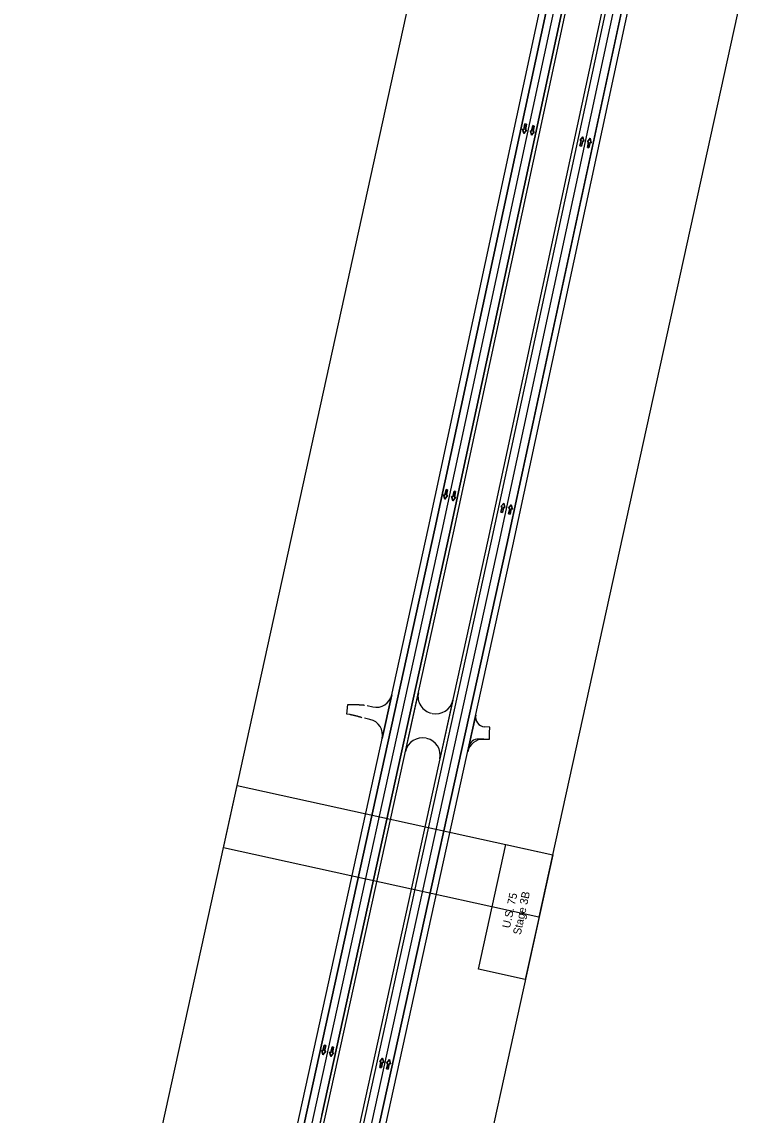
# Model space of a CAD drawing. Extents: x 14104283 to 14120882, y 8635219 to 8671666.
# Drawn here: x 14107966 to 14109111, y 8642294 to 8644002 of the extents above; entities that cross this region are included whole.
import ezdxf

# ---------------------------------------------------------------- set-up
doc = ezdxf.new("R2010")
doc.units = 0
for name, color, linetype in [('Cell', 7, 'Continuous'), ('dsnNonPlotable', 7, 'Continuous'), ('dsnPaintExistingBrokenLaneLineWhite', 7, 'Continuous'), ('dsnPaintExistingEdgeLineLeftYellow', 7, 'Continuous'), ('dsnPaintExistingEdgeLineRightWhite', 7, 'Continuous'), ('dsnShadingPaved', 7, 'Continuous'), ('dsnStgShadingPrevPav', 7, 'Continuous'), ('dsnTextOverlapEven', 7, 'Continuous')]:
    doc.layers.add(name, color=color, linetype=linetype)

msp = doc.modelspace()

# ---------------------------------------------------------------- linework, layer by layer
at = {"layer": 'Cell'}
for points in [[(14108752.6, 8643842.5), (14108755.1, 8643842), (14108753.2, 8643833.5), (14108755.1, 8643833.1), (14108750.7, 8643827.6), (14108748.9, 8643834.4), (14108750.8, 8643834)], [(14108764.7, 8643839.9), (14108767.2, 8643839.3), (14108765.3, 8643830.8), (14108767.1, 8643830.4), (14108762.7, 8643825), (14108761, 8643831.7), (14108762.8, 8643831.3)], [(14108841.1, 8643807.7), (14108838.6, 8643808.2), (14108840.5, 8643816.8), (14108838.7, 8643817.2), (14108843, 8643822.6), (14108844.8, 8643815.8), (14108842.9, 8643816.2)], [(14108852.6, 8643805.1), (14108850.2, 8643805.7), (14108852, 8643814.2), (14108850.2, 8643814.6), (14108854.6, 8643820.1), (14108856.3, 8643813.3), (14108854.5, 8643813.7)], [(14108629.2, 8643271.5), (14108631.6, 8643270.9), (14108629.8, 8643262.4), (14108631.6, 8643262), (14108627.2, 8643256.5), (14108625.5, 8643263.3), (14108627.3, 8643262.9)], [(14108641.7, 8643268.7), (14108644.1, 8643268.2), (14108642.3, 8643259.6), (14108644.1, 8643259.2), (14108639.7, 8643253.8), (14108638, 8643260.6), (14108639.8, 8643260.2)], [(14108717.5, 8643235.4), (14108715.1, 8643235.9), (14108716.9, 8643244.5), (14108715.1, 8643244.9), (14108719.5, 8643250.3), (14108721.2, 8643243.5), (14108719.4, 8643243.9)], [(14108729.3, 8643232.8), (14108726.8, 8643233.3), (14108728.7, 8643241.9), (14108726.9, 8643242.3), (14108731.2, 8643247.7), (14108733, 8643240.9), (14108731.1, 8643241.3)], [(14108438.8, 8642403.3), (14108441.2, 8642402.8), (14108439.4, 8642394.2), (14108441.2, 8642393.8), (14108436.8, 8642388.4), (14108435.1, 8642395.2), (14108436.9, 8642394.8)], [(14108451, 8642400.7), (14108453.4, 8642400.1), (14108451.6, 8642391.6), (14108453.4, 8642391.2), (14108449, 8642385.7), (14108447.3, 8642392.5), (14108449.1, 8642392.1)], [(14108528.1, 8642368.3), (14108525.7, 8642368.8), (14108527.5, 8642377.4), (14108525.7, 8642377.8), (14108530.1, 8642383.2), (14108531.8, 8642376.4), (14108530, 8642376.8)], [(14108538.8, 8642365.9), (14108536.3, 8642366.5), (14108538.2, 8642375), (14108536.3, 8642375.4), (14108540.7, 8642380.9), (14108542.5, 8642374.1), (14108540.6, 8642374.5)]]:
    msp.add_lwpolyline(points, close=True, dxfattribs=at)
for points in [[(14108750.8, 8643834), (14108748.9, 8643834.4), (14108750.7, 8643827.6), (14108755.1, 8643833.1), (14108753.2, 8643833.5), (14108755.1, 8643842), (14108752.6, 8643842.5), (14108750.8, 8643834)], [(14108762.8, 8643831.3), (14108761, 8643831.7), (14108762.7, 8643825), (14108767.1, 8643830.4), (14108765.3, 8643830.8), (14108767.2, 8643839.3), (14108764.7, 8643839.9), (14108762.8, 8643831.3)], [(14108842.9, 8643816.2), (14108844.8, 8643815.8), (14108843, 8643822.6), (14108838.7, 8643817.2), (14108840.5, 8643816.8), (14108838.6, 8643808.2), (14108841.1, 8643807.7), (14108842.9, 8643816.2)], [(14108854.5, 8643813.7), (14108856.3, 8643813.3), (14108854.6, 8643820.1), (14108850.2, 8643814.6), (14108852, 8643814.2), (14108850.2, 8643805.7), (14108852.6, 8643805.1), (14108854.5, 8643813.7)], [(14108627.3, 8643262.9), (14108625.5, 8643263.3), (14108627.2, 8643256.5), (14108631.6, 8643262), (14108629.8, 8643262.4), (14108631.6, 8643270.9), (14108629.2, 8643271.5), (14108627.3, 8643262.9)], [(14108639.8, 8643260.2), (14108638, 8643260.6), (14108639.7, 8643253.8), (14108644.1, 8643259.2), (14108642.3, 8643259.6), (14108644.1, 8643268.2), (14108641.7, 8643268.7), (14108639.8, 8643260.2)], [(14108719.4, 8643243.9), (14108721.2, 8643243.5), (14108719.5, 8643250.3), (14108715.1, 8643244.9), (14108716.9, 8643244.5), (14108715.1, 8643235.9), (14108717.5, 8643235.4), (14108719.4, 8643243.9)], [(14108731.1, 8643241.3), (14108733, 8643240.9), (14108731.2, 8643247.7), (14108726.9, 8643242.3), (14108728.7, 8643241.9), (14108726.8, 8643233.3), (14108729.3, 8643232.8), (14108731.1, 8643241.3)], [(14108436.9, 8642394.8), (14108435.1, 8642395.2), (14108436.8, 8642388.4), (14108441.2, 8642393.8), (14108439.4, 8642394.2), (14108441.2, 8642402.8), (14108438.8, 8642403.3), (14108436.9, 8642394.8)], [(14108449.1, 8642392.1), (14108447.3, 8642392.5), (14108449, 8642385.7), (14108453.4, 8642391.2), (14108451.6, 8642391.6), (14108453.4, 8642400.1), (14108451, 8642400.7), (14108449.1, 8642392.1)], [(14108530, 8642376.8), (14108531.8, 8642376.4), (14108530.1, 8642383.2), (14108525.7, 8642377.8), (14108527.5, 8642377.4), (14108525.7, 8642368.8), (14108528.1, 8642368.3), (14108530, 8642376.8)], [(14108540.6, 8642374.5), (14108542.5, 8642374.1), (14108540.7, 8642380.9), (14108536.3, 8642375.4), (14108538.2, 8642375), (14108536.3, 8642366.5), (14108538.8, 8642365.9), (14108540.6, 8642374.5)]]:
    msp.add_lwpolyline(points, dxfattribs=at)
at = {"layer": 'dsnNonPlotable'}
for points in [[(14108281.2, 8642711.6), (14108617.6, 8644242.5), (14109110.8, 8644134.2), (14108774.4, 8642603.2)], [(14107966.2, 8641278.2), (14108302.6, 8642809.2), (14108795.9, 8642700.9), (14108459.5, 8641169.9)]]:
    msp.add_lwpolyline(points, close=True, dxfattribs=at)
at = {"layer": 'dsnPaintExistingBrokenLaneLineWhite'}
for p, q in [((14108623.3, 8643207.7), (14108988, 8644901.3)), ((14108213.8, 8641343.5), (14108623.3, 8643207.7))]:
    msp.add_line(p, q, dxfattribs=at)
msp.add_lwpolyline([(14108306.4, 8641340.7), (14108389, 8641717), (14108712.3, 8643188.3), (14108894.6, 8644035.3), (14109077, 8644882.2)], dxfattribs=at)
at = {"layer": 'dsnPaintExistingEdgeLineLeftYellow'}
for p, q in [((14108700.5, 8643190.8), (14109065.3, 8644884.7)), ((14108199.6, 8640910.3), (14108700.5, 8643190.8))]:
    msp.add_line(p, q, dxfattribs=at)
msp.add_lwpolyline([(14108999.8, 8644898.8), (14108635.1, 8643205.1), (14108434.9, 8642294.1)], dxfattribs=at)
at = {"layer": 'dsnPaintExistingEdgeLineRightWhite'}
for p, q in [((14108724, 8643185.8), (14109088.7, 8644879.7)), ((14108201.6, 8640807.6), (14108724, 8643185.7))]:
    msp.add_line(p, q, dxfattribs=at)
msp.add_lwpolyline([(14108976.3, 8644903.9), (14108611.6, 8643210.2), (14108202.1, 8641346.1)], dxfattribs=at)
at = {"layer": 'dsnShadingPaved'}
for p, q in [((14108700.5, 8643190.8), (14109065.3, 8644884.7)), ((14109088.7, 8644879.7), (14108724, 8643185.8)), ((14108294.7, 8641343.2), (14108700.5, 8643190.9)), ((14108724, 8643185.7), (14108196.6, 8640785))]:
    msp.add_line(p, q, dxfattribs=at)
for points in [[(14108976.3, 8644903.9), (14108611.6, 8643210.2), (14108202.1, 8641346.1)], [(14108434.9, 8642294.1), (14108635.1, 8643205.1), (14108999.8, 8644898.8)]]:
    msp.add_lwpolyline(points, dxfattribs=at)
at = {"layer": 'dsnStgShadingPrevPav'}
for p, q in [((14108601.8, 8643212.3), (14108966.5, 8644906)), ((14108976.3, 8644903.9), (14108611.6, 8643210.2)), ((14109059.4, 8644886), (14108694.7, 8643192.1)), ((14108733.8, 8643183.6), (14109098.5, 8644877.6)), ((14108107.8, 8640963.3), (14108601.8, 8643212.3)), ((14108611.6, 8643210.2), (14108117.6, 8640961.2)), ((14108694.7, 8643192.1), (14108383, 8641773.2)), ((14108422, 8641764.6), (14108733.8, 8643183.6)), ((14108544.4, 8642950.9), (14108529.4, 8642882.6)), ((14108565.9, 8642862.3), (14108586.1, 8642954.1)), ((14108474.4, 8642920.7), (14108475.7, 8642935.7)), ((14108475.7, 8642935.7), (14108479.6, 8642935.7)), ((14108506.1, 8642933.8), (14108514.6, 8642931.9)), ((14108639.8, 8642942.3), (14108619.6, 8642850.5)), ((14108478.2, 8642920), (14108474.4, 8642920.7)), ((14108675.6, 8642919), (14108669.7, 8642892)), ((14108510.3, 8642912.3), (14108501.8, 8642914.2)), ((14108697.5, 8642900.3), (14108689.2, 8642900.9)), ((14108697.3, 8642891.3), (14108697.5, 8642900.3)), ((14108669.7, 8642892), (14108664.8, 8642869.9)), ((14108679.9, 8642881.7), (14108697, 8642881.3)), ((14108688.1, 8642881.5), (14108679.9, 8642881.7)), ((14108697, 8642881.3), (14108697.3, 8642891.3)), ((14108664.8, 8642869.9), (14108663.1, 8642861.9))]:
    msp.add_line(p, q, dxfattribs=at)
for points in [[(14108999.8, 8644898.8), (14108817.4, 8644052), (14108635.1, 8643205.1), (14108387.9, 8642080.1), (14108140.8, 8640955.1)], [(14108146.7, 8640953.8), (14108640.9, 8643203.9), (14109005.6, 8644897.6)], [(14108202.1, 8641346.1), (14108611.6, 8643210.2), (14108976.3, 8644903.9)], [(14108999.8, 8644898.8), (14108635.1, 8643205.1), (14108225.5, 8641340.9)]]:
    msp.add_lwpolyline(points, dxfattribs=at)
for centre, radius, start, end in [((14108520, 8642956.3), 25, 257.6102, 347.6102), ((14108612.4, 8642948.3), 27, 167.6102, 257.6102), ((14108613.4, 8642948.1), 27, 257.6102, 347.6102), ((14108690.3, 8642915.8), 15, 167.6102, 266.0309), ((14108505, 8642887.9), 25, 347.6102, 77.6102), ((14108592.3, 8642856.5), 27, 77.6102, 167.6102), ((14108593.2, 8642856.3), 27, 347.6102, 77.6102), ((14108687.5, 8642856.5), 25, 88.6111, 167.6102), ((14108679.5, 8642866.7), 15, 88.6102, 167.6102), ((14108679.5, 8642866.7), 15, 88.6102, 167.6102)]:
    msp.add_arc(centre, radius, start, end, dxfattribs=at)
for points in [[(14108479.6, 8642935.7), (14108480, 8642935.7), (14108480.7, 8642935.7), (14108481.8, 8642935.7), (14108482.9, 8642935.7), (14108484, 8642935.7), (14108485.1, 8642935.7), (14108486.2, 8642935.6), (14108487.3, 8642935.6), (14108488.4, 8642935.6), (14108489.5, 8642935.5), (14108490.6, 8642935.5), (14108491.8, 8642935.4), (14108492.9, 8642935.4), (14108494, 8642935.3), (14108495.1, 8642935.2), (14108496.2, 8642935.2), (14108497.3, 8642935.1), (14108498.4, 8642935), (14108499.5, 8642934.9), (14108500.6, 8642934.8), (14108501.4, 8642934.7), (14108501.7, 8642934.7)], [(14108497.8, 8642915), (14108497.5, 8642915.1), (14108496.9, 8642915.3), (14108495.9, 8642915.6), (14108494.9, 8642915.9), (14108494, 8642916.2), (14108493, 8642916.5), (14108492, 8642916.7), (14108491.1, 8642917), (14108490.1, 8642917.3), (14108489.1, 8642917.5), (14108488.1, 8642917.8), (14108487.1, 8642918), (14108486.1, 8642918.3), (14108485.1, 8642918.5), (14108484.2, 8642918.7), (14108483.2, 8642919), (14108482.2, 8642919.2), (14108481.2, 8642919.4), (14108480.2, 8642919.6), (14108479.2, 8642919.8), (14108478.5, 8642919.9), (14108478.2, 8642920)]]:
    msp.add_open_spline(points, degree=3, dxfattribs=at)
at = {"layer": 'dsnTextOverlapEven'}
for points in [[(14108795.9, 8642700.9), (14108753.1, 8642506.2), (14108679.8, 8642522.3), (14108722.6, 8642716.9)], [(14108679.8, 8642522.3), (14108722.6, 8642716.9), (14108795.9, 8642700.9), (14108753.1, 8642506.2)]]:
    msp.add_lwpolyline(points, close=True, dxfattribs=at)

# ---------------------------------------------------------------- texts
for s, p in [('Stage 3B', (14108745.8, 8642574.9)), ('U.S. 75', (14108728.9, 8642585.3))]:
    msp.add_text(s, height=12.5, rotation=77.6078, dxfattribs=at).set_placement(p)

doc.saveas('drawing.dxf')
